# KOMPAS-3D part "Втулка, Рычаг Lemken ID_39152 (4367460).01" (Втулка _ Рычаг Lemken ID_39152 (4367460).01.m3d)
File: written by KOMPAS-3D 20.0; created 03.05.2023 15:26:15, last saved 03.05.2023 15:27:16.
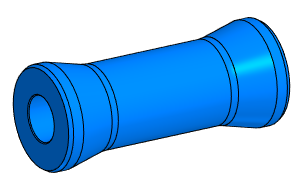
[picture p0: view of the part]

Document properties: Автор: factory; Полное имя файла: C:\Users\factory\Desktop\Чертежи\Рычаг Lemken ID_39152 (4367460)\Втулка _ Рычаг Lemken ID_39152 (4367460).01.m3d

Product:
- Part/product: Втулка  | designation Рычаг Lemken ID_39152 (4367460).01
    Материал: Сталь 40Х  ГОСТ 4543-2016 (density 7850 kg/m3)
    Масса: 8.48662
    Комментарий: Модуль генерации 3D-моделей программы <Валы и механические передачи 2D>
  - Body: Тело 1
      Масса: 8.49086

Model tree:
1. Эскиз:1
2. Внеш. контур, ступень 1: Цилиндр. D=102, L=15
     Расстояние 2 = 15; Смещение 2 = 15
3. Эскиз:2  (labels: Внеш. контур, ступень 1: Цилиндр. D=102, L=15)
4. Внеш. контур, ступень 2: Конич. d=102, D=82, L=40, A=14°02'10"
     Расстояние 1 = 40; Смещение 1 = 40; Угол 1 = 14.0362
5. Эскиз:3
6. Внеш. контур, ступень 3: Цилиндр. D=82, L=130
     Расстояние 1 = 130; Смещение 1 = 130
7. Эскиз:4  (labels: Внеш. контур, ступень 3: Цилиндр. D=82, L=130)
8. Внеш. контур, ступень 4: Конич. d=82, D=102, L=40, A=14°02'10"
     Расстояние 1 = 40; Смещение 1 = 40; Угол 1 = 14.0362
9. Эскиз:5
10. Внеш. контур, ступень 5: Цилиндр. D=102, L=15
     Расстояние 1 = 15; Смещение 1 = 15
11. Фаска:2  (labels: Внеш. контур, ступень 1: Цилиндр. D=102, L=15)
     Угол = 60; Длина 1 = 2.3094; Длина 2 = 4
12. Фаска:4  (labels: Внеш. контур, ступень 5: Цилиндр. D=102, L=15)
     Угол = 60; Длина 1 = 2.3094; Длина 2 = 4
13. Эскиз:6  (labels: Внеш. контур, ступень 1: Цилиндр. D=102, L=15)
14. Внутр. контур, ступень 1: Цилиндр. D=45, L=240
     Расстояние 1 = 240; Смещение 1 = 240
15. Фаска:5  (labels: Внутр. контур, ступень 1: Цилиндр. D=45, L=240)
     Угол = 45; Длина 1 = 1; Длина 2 = 1
16. Фаска:6  (labels: Внутр. контур, ступень 1: Цилиндр. D=45, L=240)
     Угол = 45; Длина 1 = 1; Длина 2 = 1
17. Точка:1
18. Точка:2
     X = 240; Координата X = 240
19. Осевая линия:1
20. Скругление:1
     Радиус = 30
21. Скругление:2  (labels: Внеш. контур, ступень 3: Цилиндр. D=82, L=130; Сталь 40Х  ГОСТ 4543-2016)
     Радиус = 30

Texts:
  Рычаг Lemken ID_39152 (4367460).01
